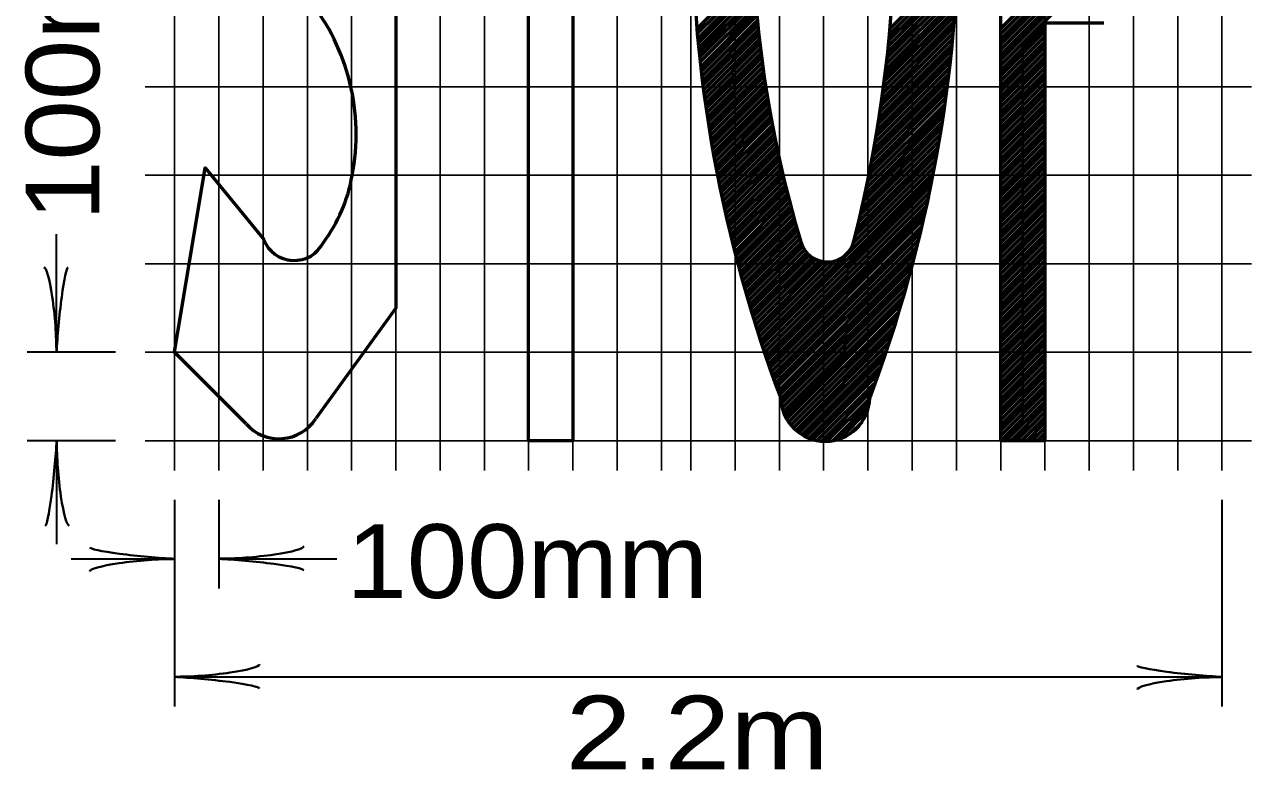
# Model space of a CAD drawing. Extents: x -96 to 617, y -65 to 388.
# Drawn here: x -13.3 to 28.29, y 318.13 to 343.37 of the extents above; entities that cross this region are included whole.
import ezdxf

# ---------------------------------------------------------------- set-up
doc = ezdxf.new("R2010")
doc.units = 0
doc.layers.add('1', color=7, linetype='Continuous', lineweight=53)

msp = doc.modelspace()

# ---------------------------------------------------------------- linework, layer by layer
at = {"layer": '1', "lineweight": 25}
for p, q in [((-8.21, 366.267), (-8.21, 328.267)), ((-6.71, 366.267), (-6.71, 328.267)), ((-5.21, 366.267), (-5.21, 328.267)), ((-3.71, 366.267), (-3.71, 328.267)), ((-2.21, 366.267), (-2.21, 328.267)), ((-0.71, 328.267), (-0.71, 366.267)), ((0.79, 366.267), (0.79, 328.267)), ((2.29, 366.267), (2.29, 328.267)), ((3.79, 366.267), (3.79, 328.267)), ((5.29, 366.267), (5.29, 328.267)), ((6.79, 366.267), (6.79, 328.267)), ((8.29, 366.267), (8.29, 328.267)), ((9.29, 366.267), (9.29, 328.267)), ((10.79, 366.267), (10.79, 328.267)), ((12.29, 366.267), (12.29, 328.267)), ((13.79, 366.267), (13.79, 328.267)), ((15.29, 366.267), (15.29, 328.267)), ((16.79, 366.267), (16.79, 328.267)), ((18.29, 366.267), (18.29, 328.267)), ((19.79, 366.267), (19.79, 328.267)), ((21.29, 366.267), (21.29, 328.267)), ((22.79, 366.267), (22.79, 328.267)), ((24.29, 366.267), (24.29, 328.267)), ((25.79, 366.267), (25.79, 328.267)), ((27.29, 366.267), (27.29, 328.267)), ((-9.21, 341.267), (28.29, 341.267)), ((-9.21, 338.267), (28.29, 338.267)), ((-9.21, 335.267), (28.29, 335.267)), ((-9.21, 332.267), (28.29, 332.267)), ((-9.21, 329.267), (28.29, 329.267))]:
    msp.add_line(p, q, dxfattribs=at)
at = {"layer": '1'}
for p, q in [((19.79, 343.235), (27.29, 350.735)), ((19.79, 343.058), (27.29, 350.558)), ((19.79, 342.881), (27.29, 350.381)), ((19.79, 342.705), (27.281, 350.195)), ((19.79, 342.528), (27.253, 349.991)), ((19.79, 342.351), (27.219, 349.78)), ((19.79, 342.174), (27.181, 349.565)), ((19.79, 341.998), (27.137, 349.344)), ((16.002, 342.845), (18.319, 345.161)), ((16.021, 343.04), (18.328, 345.347)), ((16.039, 343.235), (18.335, 345.531)), ((9.494, 343.231), (11.421, 345.157)), ((9.508, 343.068), (11.429, 344.989)), ((9.522, 342.905), (11.44, 344.823)), ((15.962, 342.451), (18.302, 344.791)), ((15.983, 342.649), (18.31, 344.976)), ((9.538, 342.745), (11.451, 344.657)), ((9.554, 342.584), (11.462, 344.492)), ((9.57, 342.423), (11.473, 344.326)), ((15.919, 342.055), (18.279, 344.415)), ((15.941, 342.253), (18.291, 344.603)), ((9.586, 342.262), (11.487, 344.163)), ((9.605, 342.104), (11.5, 344)), ((15.87, 341.652), (18.256, 344.038)), ((15.895, 341.853), (18.268, 344.226)), ((9.623, 341.945), (11.514, 343.837)), ((9.641, 341.787), (11.528, 343.674)), ((9.659, 341.628), (11.544, 343.513)), ((15.818, 341.246), (18.227, 343.655)), ((15.845, 341.45), (18.242, 343.847)), ((9.679, 341.471), (11.56, 343.352)), ((9.699, 341.314), (11.576, 343.192)), ((15.762, 340.836), (18.196, 343.271)), ((15.79, 341.041), (18.212, 343.464)), ((19.79, 341.821), (21.29, 343.321)), ((19.79, 341.644), (21.29, 343.144)), ((9.719, 341.158), (11.593, 343.031)), ((9.739, 341.001), (11.611, 342.873)), ((9.761, 340.846), (11.63, 342.715)), ((15.668, 340.212), (18.144, 342.688)), ((15.7, 340.421), (18.161, 342.882)), ((15.732, 340.63), (18.179, 343.077)), ((19.79, 341.467), (21.29, 342.967)), ((19.79, 341.29), (21.29, 342.79)), ((9.783, 340.691), (11.648, 342.556)), ((9.805, 340.537), (11.667, 342.399)), ((15.6, 339.791), (18.102, 342.293)), ((15.635, 340.003), (18.123, 342.49)), ((19.79, 341.114), (21.29, 342.614)), ((19.79, 340.937), (21.29, 342.437)), ((19.79, 340.76), (21.29, 342.26)), ((9.827, 340.382), (11.688, 342.242)), ((9.85, 340.228), (11.708, 342.086)), ((9.874, 340.075), (11.729, 341.93)), ((15.528, 339.365), (18.058, 341.896)), ((15.564, 339.578), (18.081, 342.095)), ((19.79, 340.583), (21.29, 342.083)), ((19.79, 340.406), (21.29, 341.906)), ((9.898, 339.923), (11.75, 341.775)), ((9.922, 339.77), (11.773, 341.621)), ((9.947, 339.618), (11.796, 341.467)), ((15.449, 338.932), (18.01, 341.494)), ((15.488, 339.149), (18.034, 341.695)), ((19.79, 340.23), (21.29, 341.73)), ((19.79, 340.053), (21.29, 341.553)), ((9.972, 339.466), (11.819, 341.313)), ((9.998, 339.316), (11.842, 341.16)), ((10.024, 339.165), (11.868, 341.008)), ((15.365, 338.495), (17.958, 341.088)), ((15.409, 338.716), (17.985, 341.292)), ((19.79, 339.876), (21.29, 341.376)), ((19.79, 339.699), (21.29, 341.199)), ((19.79, 339.523), (21.29, 341.023)), ((10.051, 339.014), (11.893, 340.856)), ((10.077, 338.864), (11.918, 340.705)), ((15.277, 338.054), (17.903, 340.679)), ((15.321, 338.275), (17.93, 340.884)), ((19.79, 339.346), (21.29, 340.846)), ((19.79, 339.169), (21.29, 340.669)), ((10.105, 338.715), (11.943, 340.553)), ((10.133, 338.567), (11.97, 340.404)), ((10.161, 338.418), (11.998, 340.254)), ((15.181, 337.604), (17.841, 340.264)), ((15.229, 337.829), (17.872, 340.472)), ((19.79, 338.992), (21.29, 340.492)), ((19.79, 338.815), (21.29, 340.315)), ((10.19, 338.269), (12.025, 340.105)), ((10.219, 338.122), (12.052, 339.955)), ((10.249, 337.975), (12.081, 339.808)), ((15.08, 337.149), (17.776, 339.846)), ((15.133, 337.379), (17.81, 340.056)), ((19.79, 338.639), (21.29, 340.139)), ((19.79, 338.462), (21.29, 339.962)), ((19.79, 338.285), (21.29, 339.785)), ((10.279, 337.828), (12.111, 339.66)), ((10.309, 337.681), (12.14, 339.513)), ((10.339, 337.535), (12.169, 339.365)), ((14.974, 336.69), (17.707, 339.423)), ((15.027, 336.92), (17.741, 339.634)), ((19.79, 338.108), (21.29, 339.608)), ((19.79, 337.932), (21.29, 339.432)), ((10.371, 337.39), (12.2, 339.219)), ((10.402, 337.245), (12.231, 339.074)), ((10.434, 337.1), (12.263, 338.928)), ((14.859, 336.221), (17.631, 338.994)), ((14.916, 336.455), (17.67, 339.209)), ((19.79, 337.755), (21.29, 339.255)), ((19.79, 337.578), (21.29, 339.078)), ((10.466, 336.955), (12.294, 338.783)), ((10.498, 336.811), (12.327, 338.639)), ((11.651, 332.659), (17.553, 338.562)), ((14.799, 335.984), (17.593, 338.778)), ((19.79, 337.401), (21.29, 338.901)), ((19.79, 337.225), (21.29, 338.725)), ((19.79, 337.048), (21.29, 338.548)), ((10.532, 336.667), (12.36, 338.495)), ((10.566, 336.524), (12.393, 338.352)), ((10.599, 336.381), (12.427, 338.208)), ((11.694, 332.526), (17.51, 338.342)), ((11.738, 332.394), (17.467, 338.123)), ((19.79, 336.871), (21.29, 338.371)), ((19.79, 336.694), (21.29, 338.194)), ((10.633, 336.238), (12.461, 338.066)), ((10.668, 336.096), (12.496, 337.924)), ((10.703, 335.955), (12.531, 337.783)), ((11.782, 332.26), (17.424, 337.902)), ((11.827, 332.129), (17.377, 337.678)), ((19.79, 336.517), (21.29, 338.017)), ((19.79, 336.341), (21.29, 337.841)), ((10.739, 335.813), (12.566, 337.641)), ((10.774, 335.672), (12.602, 337.5)), ((10.81, 335.531), (12.639, 337.36)), ((11.873, 331.998), (17.329, 337.454)), ((19.79, 336.164), (21.29, 337.664)), ((19.79, 335.987), (21.29, 337.487)), ((19.79, 335.81), (21.29, 337.31)), ((10.847, 335.391), (12.676, 337.221)), ((10.884, 335.251), (12.713, 337.081)), ((10.921, 335.112), (12.75, 336.941)), ((11.918, 331.866), (17.282, 337.23)), ((11.963, 331.735), (17.23, 337.001)), ((19.79, 335.634), (21.29, 337.134)), ((19.79, 335.457), (21.29, 336.957)), ((10.958, 334.972), (12.789, 336.803)), ((10.996, 334.833), (12.828, 336.665)), ((11.035, 334.695), (12.867, 336.527)), ((12.009, 331.604), (17.179, 336.773)), ((12.056, 331.474), (17.126, 336.544)), ((19.79, 335.28), (21.29, 336.78)), ((19.79, 335.103), (21.29, 336.603)), ((19.79, 334.926), (21.29, 336.426)), ((11.073, 334.557), (12.906, 336.39)), ((11.112, 334.419), (12.946, 336.253)), ((11.151, 334.281), (12.986, 336.116)), ((12.103, 331.344), (17.07, 336.311)), ((12.15, 331.214), (17.014, 336.078)), ((19.79, 334.75), (21.29, 336.25)), ((19.79, 334.573), (21.29, 336.073)), ((11.191, 334.144), (13.027, 335.981)), ((11.231, 334.008), (13.077, 335.854)), ((11.272, 333.872), (13.142, 335.741)), ((11.312, 333.735), (13.219, 335.642)), ((12.197, 331.084), (16.956, 335.843)), ((12.244, 330.955), (16.895, 335.605)), ((19.79, 334.396), (21.29, 335.896)), ((19.79, 334.219), (21.29, 335.719)), ((11.353, 333.599), (13.308, 335.555)), ((11.394, 333.464), (13.409, 335.478)), ((11.437, 333.329), (13.524, 335.417)), ((11.479, 333.195), (13.652, 335.368)), ((11.521, 333.06), (13.799, 335.338)), ((11.563, 332.926), (13.97, 335.333)), ((11.607, 332.792), (14.188, 335.373)), ((12.292, 330.826), (16.834, 335.368)), ((19.79, 334.043), (21.29, 335.543)), ((19.79, 333.866), (21.29, 335.366)), ((19.79, 333.689), (21.29, 335.189)), ((12.336, 330.694), (16.77, 335.127)), ((12.353, 330.533), (16.704, 334.884)), ((19.79, 333.512), (21.29, 335.012)), ((19.79, 333.335), (21.29, 334.835)), ((12.383, 330.386), (16.637, 334.641)), ((12.424, 330.25), (16.567, 334.394)), ((19.79, 333.159), (21.29, 334.659)), ((19.79, 332.982), (21.29, 334.482)), ((12.475, 330.125), (16.495, 334.145)), ((19.79, 332.805), (21.29, 334.305)), ((19.79, 332.628), (21.29, 334.128)), ((19.79, 332.452), (21.29, 333.952)), ((12.535, 330.008), (16.422, 333.896)), ((12.604, 329.9), (16.345, 333.642)), ((19.79, 332.275), (21.29, 333.775)), ((19.79, 332.098), (21.29, 333.598)), ((12.68, 329.799), (16.268, 333.388)), ((12.763, 329.706), (16.187, 333.13)), ((19.79, 331.921), (21.29, 333.421)), ((19.79, 331.745), (21.29, 333.245)), ((12.854, 329.621), (16.104, 332.87)), ((19.79, 331.568), (21.29, 333.068)), ((19.79, 331.391), (21.29, 332.891)), ((19.79, 331.214), (21.29, 332.714)), ((12.953, 329.542), (16.02, 332.61)), ((13.059, 329.471), (15.931, 332.344)), ((19.79, 331.037), (21.29, 332.537)), ((19.79, 330.861), (21.29, 332.361)), ((13.173, 329.409), (15.842, 332.077)), ((19.79, 330.684), (21.29, 332.184)), ((19.79, 330.507), (21.29, 332.007)), ((13.296, 329.355), (15.747, 331.807)), ((13.428, 329.31), (15.651, 331.534)), ((19.79, 330.33), (21.29, 331.83)), ((19.79, 330.154), (21.29, 331.654)), ((19.79, 329.977), (21.29, 331.477)), ((13.571, 329.277), (15.553, 331.259)), ((19.79, 329.8), (21.29, 331.3)), ((19.79, 329.623), (21.29, 331.123)), ((13.727, 329.256), (15.45, 330.979)), ((13.901, 329.253), (15.351, 330.702)), ((19.79, 329.446), (21.29, 330.946)), ((19.79, 329.27), (21.29, 330.77)), ((14.097, 329.272), (15.33, 330.505)), ((14.335, 329.333), (15.269, 330.267)), ((19.965, 329.267), (21.29, 330.593)), ((20.142, 329.267), (21.29, 330.416)), ((20.318, 329.267), (21.29, 330.239)), ((14.691, 329.513), (15.091, 329.913)), ((20.495, 329.267), (21.29, 330.062)), ((20.672, 329.267), (21.29, 329.886)), ((20.849, 329.267), (21.29, 329.709)), ((21.025, 329.267), (21.29, 329.532)), ((21.202, 329.267), (21.29, 329.355))]:
    msp.add_line(p, q, dxfattribs=at)
at = {"layer": '1', "lineweight": 35}
for p, q in [((-12.21, 332.267), (-12.21, 336.267)), ((-10.21, 332.267), (-13.21, 332.267)), ((-10.21, 329.267), (-13.21, 329.267)), ((-12.21, 329.267), (-12.21, 325.767)), ((-8.21, 327.267), (-8.21, 320.267)), ((-6.71, 327.267), (-6.71, 324.267)), ((27.29, 327.267), (27.29, 320.267)), ((-11.71, 325.267), (-8.21, 325.267)), ((-6.71, 325.267), (-2.71, 325.267)), ((-8.21, 321.267), (27.29, 321.267))]:
    msp.add_line(p, q, dxfattribs=at)
at = {"layer": '1'}
for points in [[(23.29, 343.422), (21.29, 343.422), (21.29, 329.267), (19.79, 329.267), (19.79, 365.267)], [(-5.171, 353.238), (-0.71, 347.267), (-0.71, 333.767), (-3.425, 330.023)], [(-5.783, 329.841), (-8.21, 332.267), (-7.168, 338.514), (-5.19, 336.093)]]:
    msp.add_lwpolyline(points, dxfattribs=at)
msp.add_lwpolyline([(5.29, 359.267), (5.29, 329.267), (3.79, 329.267), (3.79, 359.267)], close=True, dxfattribs=at)
for centre, radius, start, end in [((56.266, 347.267), 46.947, 159.3493, 200.6507), ((-28.579, 347.267), 46.947, 339.3493, 20.6506), ((50.476, 347.267), 39.113, 163.2793, 196.7207), ((-29.358, 347.267), 45.576, 345.7797, 14.2203), ((-9.332, 339.662), 7.278, 348.8886, 38.7494), ((-7.336, 339.128), 5.218, 323.0555, 350.4239), ((-4.156, 336.485), 1.107, 200.7604, 333.5111), ((13.912, 336.259), 0.929, 195.293, 348.3487), ((13.843, 330.76), 1.509, 181.8614, 358.1386), ((-4.673, 330.815), 1.478, 221.2766, 327.576)]:
    msp.add_arc(centre, radius, start, end, dxfattribs=at)
at = {"layer": '1', "lineweight": 40}
for centre, major_axis, ratio, start_param, end_param in [((-12.486, 333.358), (0.156, -1.786), 0.122415, 0.896353, 3.141593), ((-12.486, 333.358), (0.156, -1.786), 0.122415, 0.896353, 3.141593), ((-11.998, 333.388), (-0.176, -1.756), 0.07063, 3.140715, 5.41811), ((-11.998, 333.388), (-0.176, -1.756), 0.07063, 3.140715, 5.41811), ((-12.421, 328.147), (0.176, 1.756), 0.07063, 3.140715, 5.41811), ((-12.421, 328.147), (0.176, 1.756), 0.07063, 3.140715, 5.41811), ((-11.933, 328.176), (-0.156, 1.786), 0.122415, 0.896353, 3.141593), ((-11.933, 328.176), (-0.156, 1.786), 0.122415, 0.896353, 3.141593), ((-9.33, 325.479), (1.756, -0.176), 0.07063, 3.140715, 5.41811), ((-9.33, 325.479), (1.756, -0.176), 0.07063, 3.140715, 5.41811), ((-5.618, 325.543), (-1.786, -0.156), 0.122415, 0.896353, 3.141593), ((-5.618, 325.543), (-1.786, -0.156), 0.122415, 0.896353, 3.141593), ((-9.301, 324.991), (1.786, 0.156), 0.122415, 0.896353, 3.141593), ((-9.301, 324.991), (1.786, 0.156), 0.122415, 0.896353, 3.141593), ((-5.589, 325.056), (-1.756, 0.176), 0.07063, 3.140715, 5.41811), ((-5.589, 325.056), (-1.756, 0.176), 0.07063, 3.140715, 5.41811), ((-7.118, 321.543), (-1.786, -0.156), 0.122415, 0.896353, 3.141593), ((-7.118, 321.543), (-1.786, -0.156), 0.122415, 0.896353, 3.141593), ((26.17, 321.479), (1.756, -0.176), 0.07063, 3.140715, 5.41811), ((-7.089, 321.056), (-1.756, 0.176), 0.07063, 3.140715, 5.41811), ((-7.089, 321.056), (-1.756, 0.176), 0.07063, 3.140715, 5.41811), ((26.199, 320.991), (1.786, 0.156), 0.122415, 0.896353, 3.141593)]:
    msp.add_ellipse(centre, major_axis=major_axis, ratio=ratio, start_param=start_param, end_param=end_param, dxfattribs=at)

# ---------------------------------------------------------------- texts
at = {"layer": '1', "width": 1.1}
msp.add_text('100mm', height=2.5, rotation=90, dxfattribs=at).set_placement((-10.758, 336.721))
at = {"layer": '1'}
for s, width, p in [('100mm', 1.1, (-2.383, 323.942)), ('2.2m', 1.2, (5.048, 318.131))]:
    msp.add_text(s, height=2.5, dxfattribs=dict(at, width=width)).set_placement(p)

doc.saveas('drawing.dxf')
